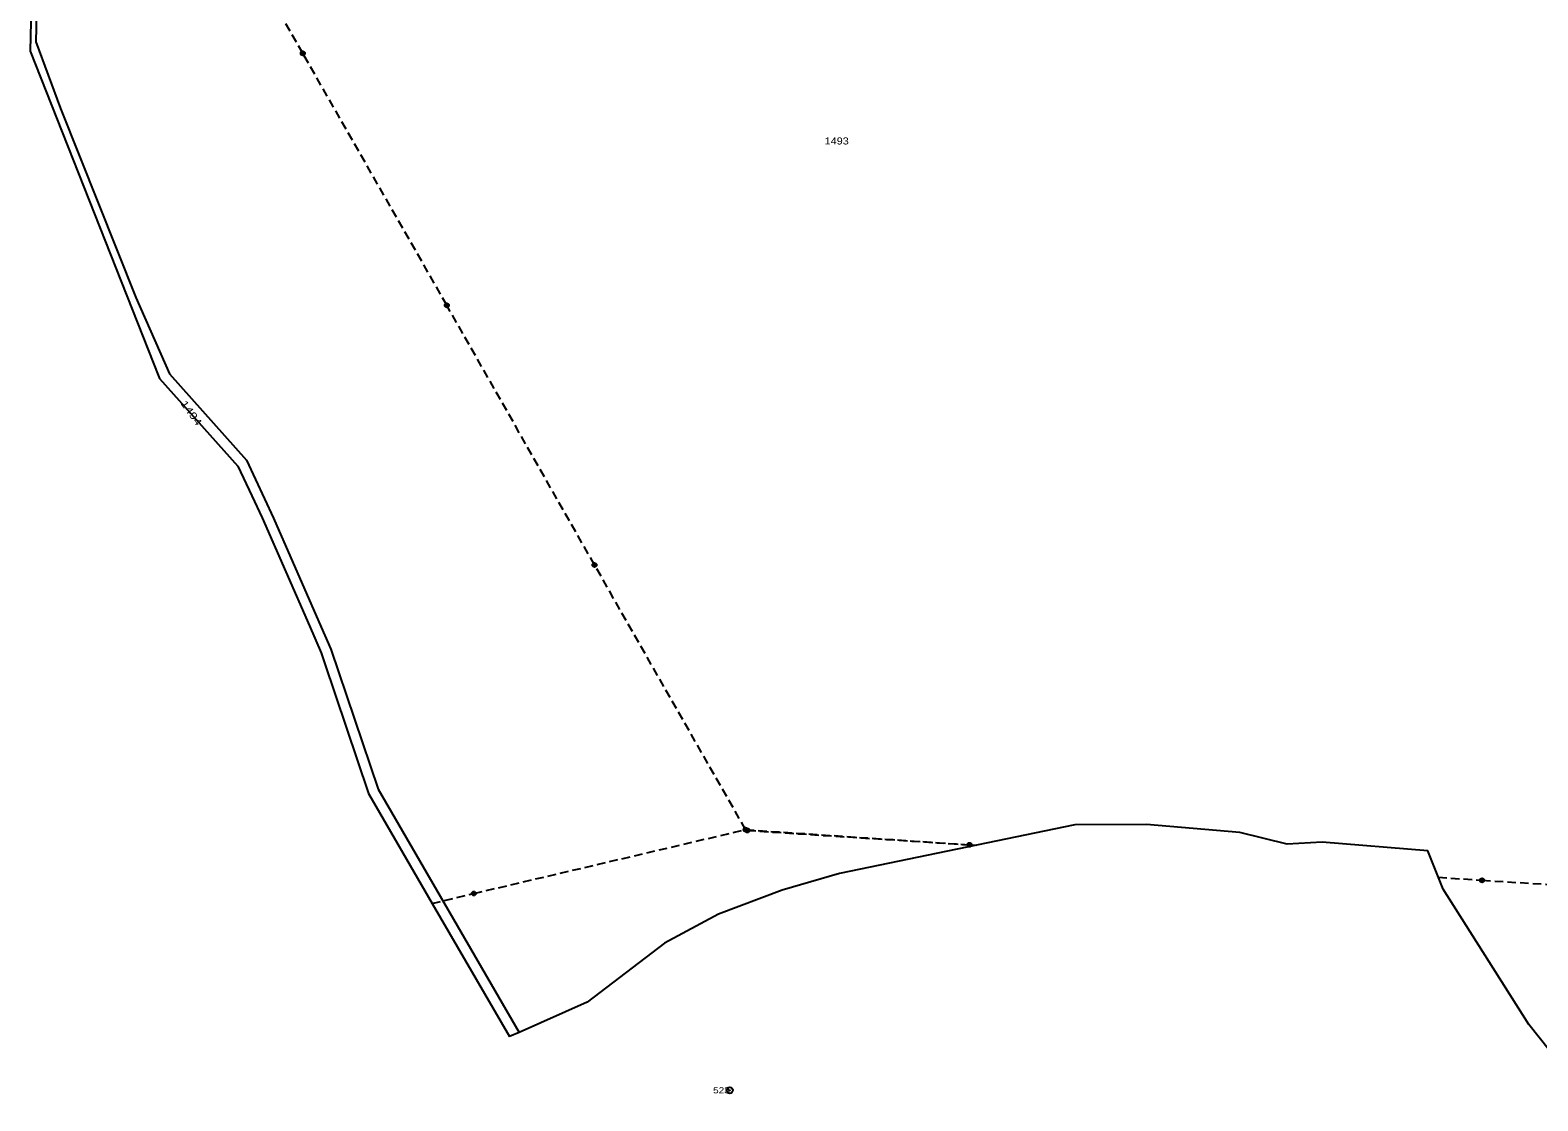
# Model space of a CAD drawing. Extents: x -872229 to -869198, y -1075981 to -1074329.
# Drawn here: x -872228.8 to -871865, y -1075164.6 to -1074906.2 of the extents above; entities that cross this region are included whole.
import ezdxf
from ezdxf.enums import TextEntityAlignment as Align

# ---------------------------------------------------------------- set-up
doc = ezdxf.new("R2010")
doc.units = 0
doc.header["$LTSCALE"] = 0.68
doc.linetypes.add('MEDIUM_DASHED', pattern=[4.5, 3, -1.5])
for name, color, linetype, lineweight in [('1', 7, 'Continuous', 25), ('6', 7, 'Continuous', 25), ('8', 7, 'Continuous', 25)]:
    doc.layers.add(name, color=color, linetype=linetype, lineweight=lineweight)
doc.layers.add('2', color=7, linetype='Continuous')

msp = doc.modelspace()

# ---------------------------------------------------------------- linework, layer by layer
at = {"layer": '1'}
for p, q in [((-871976.71, -1075098), (-872033.51, -1075109.78)), ((-872110.79, -1075148.09), (-872113.09, -1075149.11))]:
    msp.add_line(p, q, dxfattribs=at)
for points in [[(-872192.24, -1074670.26), (-872204.77, -1074711.42), (-872215.23, -1074745.5), (-872224.64, -1074784.41), (-872225.88, -1074790.78), (-872226.49, -1074800.94), (-872227.31, -1074814.6), (-872227.32, -1074846.71), (-872228.76, -1074911.36), (-872197.72, -1074989.94)], [(-872192.24, -1074670.26), (-872189.2, -1074670.7), (-872193.96, -1074682.52), (-872201.67, -1074708.83), (-872213.91, -1074748.73), (-872223.11, -1074786.33), (-872224.92, -1074808.89), (-872225.49, -1074836.22), (-872226.17, -1074857.35), (-872227.42, -1074909.07), (-872221.41, -1074925.13), (-872203.26, -1074970.76), (-872195.18, -1074989.21), (-872176.56, -1075010.03), (-872170.02, -1075024.01), (-872159.08, -1075049.04), (-872156.25, -1075055.62), (-872144.83, -1075089.41), (-872110.79, -1075148.09)], [(-872197.72, -1074989.94), (-872197.59, -1074990.27), (-872178.67, -1075011.43), (-872175.31, -1075018.6)], [(-872175.31, -1075018.6), (-872172.8, -1075023.96), (-872161.38, -1075050.03), (-872158.59, -1075056.51), (-872157.85, -1075058.71), (-872147.12, -1075090.45)], [(-872147.12, -1075090.45), (-872131.74, -1075116.96), (-872113.09, -1075149.11)], [(-871917.03, -1075102.2), (-871925.48, -1075102.69), (-871936.88, -1075099.88), (-871959.43, -1075097.95), (-871976.71, -1075098)], [(-871852.55, -1075164.62), (-871867.22, -1075146.19), (-871887.9, -1075113.56), (-871891.53, -1075104.31), (-871917.03, -1075102.2)], [(-872033.51, -1075109.78), (-872047.32, -1075113.79), (-872062.66, -1075119.57), (-872075.71, -1075126.6), (-872094.35, -1075140.79), (-872110.79, -1075148.09)]]:
    msp.add_lwpolyline(points, dxfattribs=at)
at = {"layer": '6', "linetype": 'MEDIUM_DASHED'}
for p, q in [((-872092.6, -1075035.3), (-872128.23, -1074972.65)), ((-872056.15, -1075099.17), (-872002.14, -1075102.83)), ((-872055.75, -1075099.37), (-872002.14, -1075102.83)), ((-872002.14, -1075102.83), (-872000.53, -1075102.94)), ((-871889.04, -1075110.65), (-871878.47, -1075111.4)), ((-871878.47, -1075111.4), (-871781.31, -1075117.39)), ((-872131.74, -1075116.96), (-872121.72, -1075114.58))]:
    msp.add_line(p, q, dxfattribs=at)
for points in [[(-872128.23, -1074972.65), (-872162.98, -1074911.84), (-872203.32, -1074841.42)], [(-872121.72, -1075114.58), (-872056.15, -1075099.17), (-872092.6, -1075035.3)]]:
    msp.add_lwpolyline(points, dxfattribs=at)
at = {"layer": '6'}
for centre, radius in [((-872162.9834, -1074911.8399), 0.5), ((-872162.9834, -1074911.8399), 0.4), ((-872162.9834, -1074911.8399), 0.3), ((-872162.9834, -1074911.8399), 0.2), ((-872162.9834, -1074911.8399), 0.1), ((-872128.2334, -1074972.6499), 0.5), ((-872128.2334, -1074972.6499), 0.4), ((-872128.2334, -1074972.6499), 0.3), ((-872128.2334, -1074972.6499), 0.2), ((-872128.2334, -1074972.6499), 0.1), ((-872092.6034, -1075035.2999), 0.5), ((-872092.6034, -1075035.2999), 0.4), ((-872092.6034, -1075035.2999), 0.3), ((-872092.6034, -1075035.2999), 0.2), ((-872092.6034, -1075035.2999), 0.1), ((-872056.1534, -1075099.1699), 0.5), ((-872056.1534, -1075099.1699), 0.4), ((-872056.1534, -1075099.1699), 0.3), ((-872056.1534, -1075099.1699), 0.2), ((-872055.7534, -1075099.3699), 0.5), ((-872056.1534, -1075099.1699), 0.1), ((-872055.7534, -1075099.3699), 0.4), ((-872055.7534, -1075099.3699), 0.3), ((-872055.7534, -1075099.3699), 0.2), ((-872055.7534, -1075099.3699), 0.1), ((-872002.1434, -1075102.8299), 0.5), ((-872002.1434, -1075102.8299), 0.4), ((-872002.1434, -1075102.8299), 0.3), ((-872002.1434, -1075102.8299), 0.2), ((-872002.1434, -1075102.8299), 0.1), ((-871878.4734, -1075111.3999), 0.5), ((-871878.4734, -1075111.3999), 0.4), ((-871878.4734, -1075111.3999), 0.3), ((-871878.4734, -1075111.3999), 0.2), ((-871878.4734, -1075111.3999), 0.1), ((-872121.7234, -1075114.5799), 0.5), ((-872121.7234, -1075114.5799), 0.4), ((-872121.7234, -1075114.5799), 0.3), ((-872121.7234, -1075114.5799), 0.2), ((-872121.7234, -1075114.5799), 0.1)]:
    msp.add_circle(centre, radius, dxfattribs=at)
at = {"layer": '8'}
for radius in [0.75, 0.03]:
    msp.add_circle((-872059.98, -1075162.0698), radius, dxfattribs=at)

# ---------------------------------------------------------------- texts
at = {"layer": '2', "width": 1.15}
msp.add_text('1493', height=1.7, dxfattribs=at).set_placement((-872037.08, -1074933.84))
at = {"layer": '2', "width": 1.35}
msp.add_text('1494', height=1.7, rotation=306, dxfattribs=at).set_placement((-872192.567, -1074996.359))
at = {"layer": '8', "width": 1.2}
msp.add_text('523', height=1.5, dxfattribs=at).set_placement((-872059.98, -1075162.82), align=Align.RIGHT)

doc.saveas('drawing.dxf')
